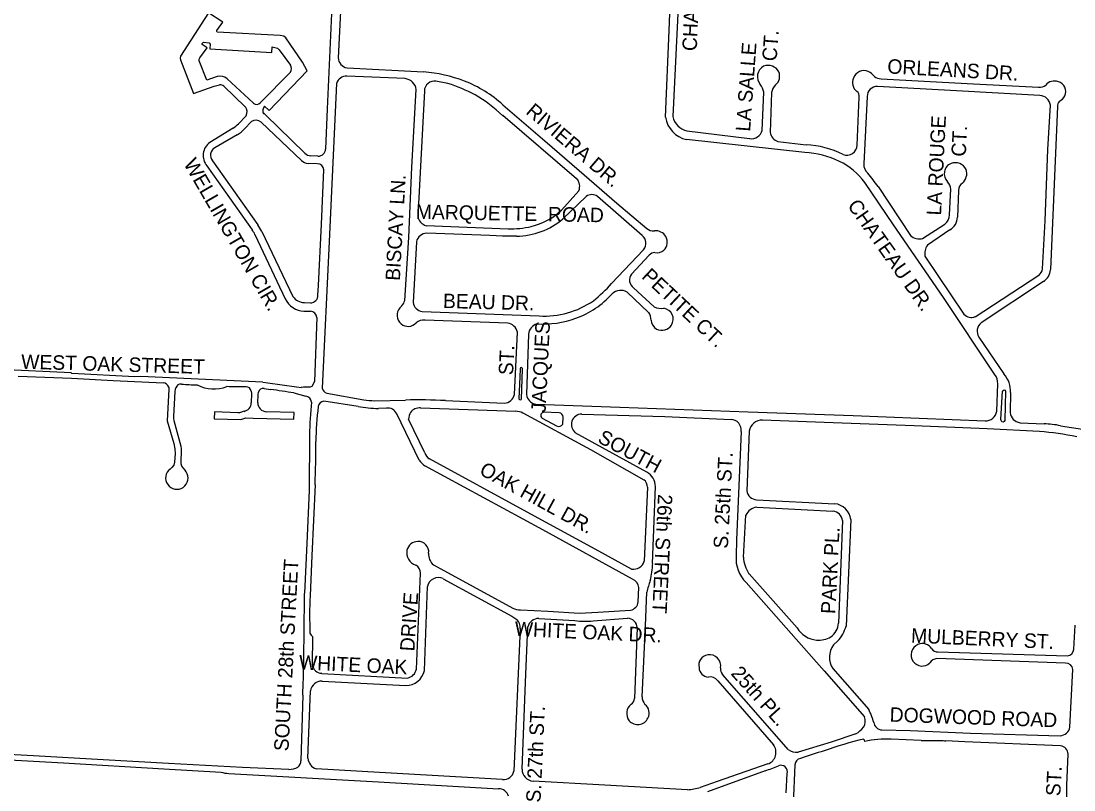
# Model space of a CAD drawing. Extents: x 0 to 712119, y 0 to 761125.
# Drawn here: x 674515 to 678156, y 731363 to 734022 of the extents above; entities that cross this region are included whole.
import ezdxf

# ---------------------------------------------------------------- set-up
doc = ezdxf.new("R2010")
doc.units = 0
doc.layers.add('PAVED ROADS', color=7, linetype='Continuous')
doc.layers.add('street names', color=7, linetype='Continuous')

msp = doc.modelspace()

# ---------------------------------------------------------------- linework, layer by layer
at = {"layer": 'PAVED ROADS'}
for points in [[(675652.2, 735319), (675637.3, 735042.7), (675627.5, 734773.9), (675618.5, 734577.2), (675593, 734058.8), (675589.4, 734048.4), (675573.9, 733717.9), (675568.3, 733578.6)], [(676743.3, 733689), (676756.4, 733989.1), (676770.1, 734344.8), (676784.9, 734648.6)], [(676811.5, 734637.9), (676790.9, 734143.3), (676768.9, 733691.7)], [(675643.4, 734593), (675628.8, 734239.8), (675611.9, 733895)], [(675357.3, 733727.5), (675373.1, 733713), (675505.1, 733849.5), (675488.9, 733879.7), (675430.4, 733963.3), (675424.3, 733970.1), (675411.8, 733971.3), (675194, 733983.8), (675192.2, 733985.5), (675192.9, 733988.9), (675213.1, 734018.2), (675163.7, 734050.5), (675066.3, 733900.6), (675065.2, 733893.5), (675066.8, 733887.7), (675111.2, 733770.7), (675183.5, 733797), (675202.1, 733801.4)], [(675194, 733829.7), (675157.6, 733817.3), (675131.6, 733884.1), (675131.1, 733890.5), (675133.3, 733894.8), (675158.7, 733929.1), (675141.5, 733941.2), (675141.9, 733944.6), (675145.8, 733948.4), (675166, 733946.4), (675169.7, 733941.6), (675168.2, 733925.4), (675382.5, 733913.5), (675384, 733932.7), (675393.4, 733930.9), (675401.8, 733928.1), (675408.4, 733922.7), (675446.8, 733869.8)], [(675446.7, 733845.2), (675343.8, 733739.9)], [(675642.9, 733860.2), (675907.1, 733846.1)], [(675317.5, 733738.7), (675228.3, 733822.5)], [(675606.7, 733806.3), (675581.1, 733258.9), (675557, 732752.4)], [(675843.6, 733822.7), (675642, 733831.2)], [(675991.3, 733806), (675949.9, 733814.1)], [(677489.1, 733822.2), (677787.1, 733806.1), (678033.7, 733793.3)], [(675216.8, 733797.1), (675290.9, 733725.1)], [(675841.9, 733055.6), (675855.9, 733272.9), (675866.6, 733516.4), (675881.6, 733784.8)], [(675909.9, 733780.6), (675887.1, 733346)], [(677077.7, 733643.8), (677083.6, 733775.9)], [(677110.8, 733774.5), (677105.6, 733636.7)], [(678038, 733763.9), (677749.6, 733780.1), (677477.2, 733795.3)], [(676181.6, 733732), (676326.5, 733607.9), (676444.7, 733505.1), (676575.8, 733391.9), (676679, 733304.6)], [(677406.7, 733592.9), (677413.5, 733758.6)], [(677441, 733761.2), (677429.4, 733527.6)], [(678047.8, 733164.4), (678056.2, 733331.1), (678066.1, 733577.2), (678074.5, 733730.9)], [(675293.3, 733693.7), (675266.9, 733666.8)], [(675496.9, 733564.5), (675360.2, 733697.6), (675355.9, 733702.5), (675353.5, 733700.9)], [(676436.4, 733476.5), (676181.2, 733694.6)], [(678099.1, 733726.2), (678075.1, 733162)], [(675312.6, 733674.1), (675287.6, 733649.3)], [(675484.7, 733540.1), (675345.3, 733672.2)], [(675248.3, 733651.6), (675168.6, 733602.2)], [(675262.9, 733627.8), (675185.8, 733583.4)], [(676817.9, 733641.9), (677034.7, 733615.4)], [(677225.1, 733567.1), (676816.7, 733612)], [(677132.4, 733605.3), (677229.9, 733594.2)], [(675542.1, 733554.8), (675516.4, 733556.1)], [(675158.1, 733521.3), (675314.5, 733300.1)], [(675177.9, 733538.7), (675333.8, 733317.3), (675333.8, 733317.3)], [(675539.7, 733528.5), (675508.1, 733529.3)], [(675542, 733074.2), (675543.4, 733107.6), (675554.3, 733319), (675562.5, 733506.7)], [(677881.8, 732800.1), (677704.8, 733065.3), (677531.6, 733316.8), (677432.8, 733463.1)], [(677478.7, 733449.7), (677591.4, 733280.3)], [(677725.6, 733351.4), (677730.3, 733440.2)], [(676383.9, 733368.2), (676443.9, 733435)], [(676469.2, 733415.3), (676389.2, 733337.7)], [(676663.4, 733280.4), (676509, 733415.1)], [(677757.2, 733436.1), (677753.1, 733343.8)], [(675347.8, 733294.2), (675455.6, 733068.9)], [(675915.7, 733314.2), (676199.5, 733303.3)], [(677632.9, 733270.3), (677710.1, 733319)], [(677726.8, 733300.1), (677649.4, 733246.7)], [(675324.2, 733283.5), (675429.2, 733061.1)], [(675882.5, 733258.8), (675870.9, 733047.9)], [(676228.4, 733277.3), (676180.3, 733277.9), (676136.7, 733280.1), (675918.4, 733288.2)], [(676557.4, 733114.6), (676667.9, 733231)], [(676687.8, 733211.7), (676626.4, 733146.2)], [(677640.9, 733208.6), (677775.7, 733007.9)], [(677814.7, 732999.4), (678035, 733142.4), (678035, 733142.4)], [(678050.5, 733121.2), (677835.1, 732978.1)], [(676685.5, 733013.9), (676611, 733084.6)], [(676633.3, 733099.6), (676704.7, 733033.3)], [(675494.9, 733048.1), (675515.9, 733046.8)], [(676494.4, 733054.7), (676494.4, 733054.7)], [(676494.4, 733054.7), (676494.4, 733054.7)], [(675493.5, 733018.2), (675516.2, 733018.6)], [(675824.8, 733029.8), (675832.5, 733036.9)], [(675901.9, 733017), (676306.8, 733001.8)], [(675538.2, 732996.2), (675529.5, 732774.7), (675521.1, 732758.4), (675514.8, 732755.2)], [(676198, 732977.4), (675912.1, 732987), (675912.1, 732987)], [(676221.4, 732730.3), (676231.5, 732945.9)], [(676269.7, 732938.7), (676263.1, 732729.8)], [(677827.4, 732929), (677913.9, 732801.4)], [(675351.8, 732772.4), (674929.5, 732793), (674908.9, 732791.2), (674690.8, 732802.7), (674688.2, 732805.3), (674442.7, 732816.9)], [(674505.8, 732794.2), (674689.4, 732786.7), (674833.5, 732778.8), (675006.8, 732771)], [(676241.1, 732818.3), (676236.9, 732714.8)], [(676246.2, 732714.8), (676249.1, 732818.3)], [(675026.1, 732755.9), (675026.5, 732748.2), (675021, 732638.7), (675043.8, 732561.2), (675047.7, 732542), (675048, 732526.6), (675046.5, 732496.8), (675043.1, 732485.8), (675036.5, 732477.3), (675030.7, 732472.4)], [(675086.5, 732462.6), (675082.9, 732468.6), (675076.7, 732475.3), (675071.8, 732482.3), (675069.4, 732490.6), (675068.9, 732496.2), (675070.5, 732536.6), (675070.1, 732543.3), (675068.8, 732550.8), (675045.4, 732638.9), (675043.8, 732648), (675043.9, 732653.8), (675048.8, 732741.1), (675049.2, 732747.1), (675050.8, 732753.4)], [(675355.6, 732751.4), (675378.1, 732748.1)], [(675484.5, 732754.8), (675484.5, 732754.8)], [(677889.2, 732672.9), (677892.3, 732767.1)], [(675311.1, 732741.9), (675312.5, 732733.5), (675311.1, 732701.2)], [(675334, 732702), (675334.9, 732729.4), (675336.2, 732738.7)], [(675458.7, 732735.6), (675500.1, 732724.8)], [(675572.9, 732735), (675700.2, 732711.4)], [(675737.5, 732708.7), (675844.5, 732711.1)], [(677936.9, 732736.6), (677935.8, 732668.5)], [(675680.7, 732688.6), (675562.7, 732707.3)], [(675778.8, 732682.8), (675751.3, 732682.3)], [(675896.8, 732683.7), (676226.1, 732672.5)], [(675983, 732709.1), (676186.2, 732700.2)], [(676295.7, 732697.2), (676586.2, 732686.7), (677029.4, 732670.7), (677392.8, 732657.2), (677848.5, 732639)], [(675286.7, 732672.1), (675270.8, 732667.4), (675265.2, 732667.3), (675184.6, 732669.8), (675182.9, 732646.1), (675275, 732643.9), (675292.6, 732649.5), (675317.8, 732648.9), (675458.8, 732645.2), (675459.5, 732668.4), (675364.1, 732670.7)], [(675891.9, 732502.9), (675814.2, 732663.6)], [(675911.2, 732528.3), (675855.5, 732644.7)], [(676250.6, 732666.3), (676484.5, 732539.7), (676669.1, 732435.2)], [(676317.2, 732648.9), (676367, 732621.6)], [(676375.9, 732666.9), (676322.1, 732668.6)], [(676375.9, 732666.9), (676375.9, 732666.9)], [(676388.6, 732627.8), (676390.2, 732652.2)], [(676454.1, 732662.7), (676741.3, 732653.6), (676970.3, 732644.3)], [(678036.5, 732602.1), (677855.7, 732611.5), (677603.7, 732621.8), (677292.4, 732632.9), (677079, 732641.3)], [(677005.4, 732602.4), (676988.8, 732227.6), (676987.8, 732172.6)], [(677033.3, 732603.6), (677024.8, 732397)], [(677969.9, 732632.8), (678053, 732628.9)], [(678109.2, 732622.2), (678185.1, 732610.3)], [(675513, 732590), (675512, 732399), (675503.2, 732214.7), (675495.5, 732042.6)], [(676679.7, 732461.1), (676431.9, 732598.1)], [(676626.6, 732126.5), (676512.9, 732188.3), (676265.3, 732323.6), (675927.2, 732507.3)], [(676629.8, 732091.5), (676319.1, 732261.9), (675911.5, 732483.8)], [(675531.9, 732418.3), (675520.6, 732173.4), (675514.7, 732034.4)], [(676681, 732409.4), (676670.2, 732154)], [(676699.3, 732145.8), (676709.1, 732412)], [(677058.4, 732365.8), (677328.9, 732352.6)], [(677013, 732167.9), (677021.3, 732313.4)], [(677059, 732340.6), (677322.9, 732327.3)], [(677356, 732294), (677342, 731939.2)], [(677384.6, 732297.5), (677367.9, 731929.3)], [(675941.5, 732141), (676078.9, 732066.5), (676215.4, 731991.5)], [(675882.2, 731780.7), (675896.1, 732112.3)], [(675974.7, 732093.3), (676212.1, 731963.5), (676230, 731952.6)], [(675974.7, 732093.3), (675974.7, 732093.3)], [(677198.9, 731922.9), (677032.5, 732109.9), (677032.5, 732109.9)], [(675910.2, 731775.8), (675921.2, 732066)], [(676649.4, 732012.9), (676651.5, 732063)], [(677022.3, 732080.3), (677178.7, 731903.9), (677292.4, 731774.3), (677431.3, 731615)], [(676662.7, 731684.8), (676674.4, 731930.4), (676679, 732046.6)], [(676242.1, 731985.8), (676336.4, 731980.9), (676446.2, 731974.2), (676510, 731977.5), (676622.9, 731984.5)], [(676305.2, 731955.7), (676430.2, 731948.1)], [(676493.7, 731947.3), (676612.5, 731956.4)], [(676240.9, 731920.6), (676219.8, 731427.3)], [(676247.8, 731434.1), (676259.8, 731735.8), (676267.3, 731927)], [(676646.1, 731923.9), (676636, 731679)], [(678156, 731849.9), (678160.6, 731932.7)], [(675523.7, 731893.6), (675522.3, 731795.3)], [(677338.8, 731877.7), (677324.8, 731864.1)], [(677685.6, 731840.3), (678132.4, 731826.1), (678132.4, 731826.1)], [(678126.5, 731801.6), (677681.6, 731817.2)], [(675555.1, 731765.9), (675851.1, 731749.7)], [(677322.1, 731782.7), (677446.4, 731640.3)], [(678142.2, 731580), (678152.1, 731779.2)], [(675556.2, 731738.9), (675845.7, 731723.5)], [(676924.2, 731739.8), (677117, 731519.1)], [(677168, 731503), (677088.6, 731593.4), (676941.1, 731762.4)], [(675489.7, 731690.5), (675483.2, 731463.2)], [(675507.5, 731472.3), (675516.1, 731705.8)], [(677402.3, 731556.4), (677316, 731528), (677202, 731493.5)], [(677491.9, 731570.1), (677590, 731567.7), (677798.6, 731558.9), (678108.4, 731549.8)], [(677627.5, 731534), (677524.4, 731538)], [(678109.5, 731515), (677778.5, 731529.5), (677713.4, 731533)], [(674172.6, 731477.8), (674349.6, 731473.2), (674661.6, 731456.3), (675009, 731435.2), (675207, 731424.2)], [(675441.3, 731433.7), (675281.2, 731440.6), (675024.7, 731454), (674799.1, 731466.4), (674558.3, 731481.1), (674280, 731495.2)], [(678130, 731190.5), (678131.5, 731379), (678136, 731486.5)], [(676180.5, 731398.5), (675754.5, 731423.5), (675535.5, 731435.5)], [(677098, 731452.5), (676922, 731392), (676864, 731371.5)], [(677190.5, 731450), (677185, 731313)], [(675233.5, 731419.7), (675751.7, 731390.3), (676166.8, 731366.9)], [(677088.5, 731428.4), (676888.6, 731356)], [(677161.5, 731352.5), (677164.5, 731419)], [(676820, 731363.5), (676534, 731379.5), (676286.5, 731393)]]:
    msp.add_lwpolyline(points, dxfattribs=at)
msp.add_lwpolyline([(677915, 732746), (677918.7, 732744.8), (677919.9, 732742), (677916.9, 732640.4), (677914.3, 732636.5), (677910.8, 732634.8), (677907.1, 732636.2), (677904.3, 732640.2), (677903.8, 732644.1), (677909.2, 732741.8), (677911.3, 732744.6)], close=True, dxfattribs=at)
for centre, radius, start, end in [((675647.6, 733895.7), 35.8, 181.1063, 262.3574), ((675427.6, 733857.6), 22.7, 326.7538, 32.4129), ((675863.5, 733319.3), 528.6, 69.4388, 85.2607), ((677102.1, 733829.5), 40.7, 117.8036, 221.238), ((677099, 733827.9), 40.7, 26.4491, 112.8896), ((677100.2, 733830.7), 38.4, 309.0638, 23.5384), ((677430.2, 733811.2), 39.1, 67.8293, 159.5623), ((677415.2, 733789.8), 64.9, 38.282, 62.7128), ((675204, 733792), 39, 51.5443, 104.8205), ((675640.1, 733796.3), 34.9, 86.9787, 163.3541), ((675839.7, 733780.8), 42.1, 5.376, 84.6785), ((675945.4, 733778.8), 35.6, 82.7111, 177.0378), ((675791.7, 733193.7), 644, 62.8509, 71.944), ((675892.4, 733414.2), 429.6, 47.702, 68.6129), ((677014.7, 733760.8), 70.5, 12.3455, 36.3415), ((677431.2, 733809.4), 40.7, 157.6485, 230.1123), ((677493.8, 733874), 52, 237.9363, 264.8852), ((678088.1, 733775.8), 38.5, 68.4961, 140.7166), ((678093, 733778), 34.9, 334.9812, 74.6891), ((675203.4, 733778.8), 22.7, 53.8442, 93.2968), ((675782.9, 733266.6), 584.6, 47.06, 58.8231), ((677156, 733767.8), 45.8, 133.699, 171.5813), ((677394.8, 733762.2), 19.1, 349.2433, 57.057), ((677475.3, 733761), 34.3, 86.9844, 179.682), ((678037.6, 733827), 33.9, 263.499, 307.8141), ((675319.5, 733739.4), 2.14, 199.8502, 231.3778), ((675329.9, 733752.3), 18.7, 231.3778, 318.1777), ((678037.9, 733727.1), 36.8, 5.8627, 89.8687), ((678128.5, 733726.2), 29.4, 142.4675, 179.9221), ((678086.8, 733782.2), 42.3, 295.7747, 333.4424), ((675268.8, 733707.6), 28.2, 330.3899, 38.3732), ((675374.2, 733711.5), 23.2, 136.6053, 207.2551), ((675186.7, 733746), 112.7, 303.119, 315.3728), ((675327.6, 733650.7), 27.9, 50.5728, 122.5743), ((676837.6, 733705.4), 95.7, 189.8361, 257.4042), ((676833.2, 733705.9), 65.9, 192.4425, 256.537), ((675194.4, 733731.2), 124, 303.5207, 318.6947), ((677040.8, 733653), 38, 260.8956, 346.0059), ((677144, 733642.3), 38.8, 188.3597, 252.5533), ((675199.8, 733557), 54.9, 124.637, 220.5561), ((675198.4, 733558.1), 28.3, 116.6622, 223.4804), ((677211.8, 733266.9), 327.8, 63.5385, 86.8327), ((677371.2, 733593.2), 35.5, 247.8932, 359.4094), ((675517.9, 733586), 30, 225.77, 267.27), ((675543.3, 733579.8), 25, 267.27, 357.27), ((677211.4, 733263.1), 304.3, 63.9305, 87.4151), ((675512.3, 733568.9), 39.9, 226.2483, 263.909), ((675539.5, 733505.5), 23, 3.0595, 89.4272), ((677251.5, 733335.3), 221.8, 35.1621, 65.047), ((677469.4, 733525.7), 40, 177.2223, 229.6471), ((677745.8, 733493.9), 38.5, 112.3661, 226.5194), ((677745.2, 733489.9), 42.1, 26.114, 109.5804), ((676409.3, 733450.2), 37.8, 336.4498, 44.1708), ((676316.8, 732587.1), 1447.1, 36.5897, 38.8661), ((677742.9, 733494.2), 42.5, 309.9211, 19.56), ((677687.2, 733437), 43.2, 4.2668, 42.128), ((677790, 733435.4), 32.8, 126.9928, 178.8692), ((676489, 733388.1), 33.6, 53.3559, 126.133), ((676230, 733527), 221.2, 282.9575, 314.0964), ((675927.1, 733353.2), 40.7, 190.2197, 253.6345), ((676223.5, 733534.7), 257.4, 271.083, 310.0681), ((677675.8, 733355.3), 50, 313.4119, 355.4929), ((677703.3, 733344), 49.8, 298.1983, 359.7485), ((675224.7, 733236.6), 110, 25.27, 35.27), ((675198.6, 733219.8), 166.7, 26.5049, 35.7949), ((676208.7, 733611.7), 308.5, 268.3018, 283.2796), ((676700.8, 733329), 32.8, 228.1546, 277.6857), ((676708.8, 733253.8), 42.9, 32.3425, 94.73), ((675919.8, 733249.8), 38.4, 92.0928, 166.5044), ((676639.9, 733253.4), 35.8, 321.3942, 49.0431), ((676709.6, 733257.8), 40.2, 315.1427, 28.1229), ((677620.7, 733310.9), 42.4, 226.2029, 286.739), ((676705.1, 733200.1), 20.8, 85.1682, 146.2518), ((676714.1, 733255.8), 35.7, 258.3652, 312.2399), ((677688.7, 733218), 48.7, 143.8222, 191.1188), ((678004.7, 733174.7), 44.3, 313.0845, 346.6018), ((678021.7, 733166.3), 53.5, 302.4864, 355.3571), ((676244.3, 733380.7), 410.9, 307.5021, 319.6362), ((676650.9, 733126), 31.7, 140.4101, 236.337), ((675514.5, 733074.3), 27.5, 272.9977, 359.7926), ((676325.1, 733290.3), 315.8, 290.1347, 317.8659), ((676589.4, 733046.9), 43.5, 60.2005, 133.6146), ((675497, 733093.1), 75, 205.27, 267.27), ((675494.8, 733095.4), 47.2, 214.0471, 270.149), ((675805.6, 733062.2), 36.9, 316.8125, 349.735), ((675907.5, 733053.7), 37.1, 188.8657, 261.221), ((676323.9, 733300.3), 299, 266.7254, 304.7771), ((675515.1, 732995.4), 23.1, 1.9088, 87.3388), ((675855.1, 733004.5), 39.5, 140.1132, 229.0189), ((676649.4, 732988), 44.5, 358.9922, 35.694), ((676730.2, 733090.5), 62.7, 245.9104, 277.2193), ((676732.3, 732990.8), 38, 327.8349, 81.205), ((677801.5, 733032.5), 35.6, 223.7731, 291.8248), ((675853.7, 733004.2), 38.3, 230.3108, 317.3506), ((675905.2, 732954.5), 33.2, 77.9027, 134.6007), ((676192.5, 732938), 39.8, 11.5163, 82.049), ((676311.7, 732934.4), 42.2, 106.9099, 174.1988), ((676322, 733301.3), 327.3, 266.0564, 289.9889), ((676732.5, 732990.1), 38.7, 184.2934, 239.9138), ((676731, 732992.1), 39.8, 243.2654, 327.231), ((677858.6, 732949.2), 37.2, 129.1035, 212.9711), ((676245.1, 732819.1), 4.07, 348.5463, 192.0652), ((677847.5, 732771), 45, 355.004, 40.2416), ((677847, 732741.2), 90, 357.09, 42.0009), ((675005.1, 732748.9), 22.2, 18.3413, 85.5429), ((675068.4, 732747.8), 18.6, 85.581, 162.1926), ((675139.4, 733547.5), 784.3, 264.9165, 268.9035), ((675182.4, 732875.7), 126.5, 242.6871, 290.7161), ((675206.8, 728398.5), 4358.9, 88.8635, 89.7321), ((675294.6, 732740), 16.6, 6.5677, 94.6132), ((675352.3, 732735.3), 16.4, 78.2767, 168.0579), ((679549.8, 763896.8), 31406.2, 262.31841, 262.5627), ((674363.5, 725937.6), 6885.6, 80.84787, 81.52596), ((675501.1, 732649.1), 107, 82.6675, 98.9424), ((675578.3, 732755.7), 21.5, 188.873, 255.4961), ((675496.4, 732701.9), 23.3, 5.9048, 80.7137), ((675741.9, 733026.5), 317.8, 262.4569, 269.2161), ((675889.8, 731072.6), 1639.1, 86.7392, 91.5842), ((676184.2, 732738.1), 38, 272.9263, 348.1652), ((676241.6, 732716.9), 5.1, 203.3617, 336.2201), ((676299.8, 732734), 37, 186.4758, 263.5534), ((675281.9, 732700.8), 29.2, 279.5364, 0.7653), ((675365, 732701.7), 31.1, 179.4419, 268.3504), ((676879.3, 732568.6), 1366.5, 174.3033, 179.104), ((676580.2, 732554.8), 1045.8, 172.6506, 179.31), ((675566.8, 732683.3), 24.4, 99.7837, 167.3358), ((675751.4, 733078.2), 395.9, 259.7237, 269.9979), ((675784.7, 732651.4), 31.9, 22.4585, 100.5998), ((675892.7, 732646.3), 37.6, 83.7236, 143.8939), ((675896.7, 732645.6), 41.3, 146.4839, 181.3167), ((676224.2, 732613.5), 59, 63.3714, 88.1307), ((676323, 732657.9), 10.7, 94.3193, 237.4598), ((676373.5, 732650.3), 16.9, 6.5014, 81.6123), ((676454.8, 732626.4), 36.4, 91.1249, 230.93), ((676968.5, 732607.2), 37.2, 352.5695, 87.3339), ((677076.3, 732598.1), 43.4, 86.5043, 172.7132), ((677849.4, 732679.3), 40.3, 268.7154, 350.9241), ((677973.1, 732670), 37.3, 182.3202, 265.1013), ((676374.6, 732636), 16.3, 242.2286, 329.5719), ((677947.4, 731478.9), 1126.8, 78.8034, 85.4651), ((678043, 732309.1), 320, 78.0495, 88.2127), ((672688.1, 732541.7), 2846.5, 357.5141, 0.5169), ((675530.7, 732567.5), 3.74, 358.7249, 358.8022), ((675958.6, 732547.9), 51.3, 202.4264, 232.2873), ((675951.5, 732544.5), 72.7, 214.9326, 236.6011), ((675054, 732441.3), 38.9, 126.7873, 33.1534), ((676649.4, 732409.6), 59.8, 2.3208, 59.5228), ((676653.2, 732412.2), 27.9, 354.2968, 55.3129), ((677061.9, 732403.3), 37.7, 189.7135, 264.6662), ((677322.6, 732290.6), 62.3, 6.3952, 84.2465), ((677066, 732291.3), 49.8, 98.0569, 153.626), ((677317.1, 732288.4), 39.3, 8.1404, 81.4161), ((675887.7, 732182.8), 39.1, 91.1765, 166.5834), ((675889.1, 732185.9), 36, 352.7831, 93.4229), ((675894.4, 732183.7), 45.5, 169.6736, 251.9465), ((675972.4, 732177.4), 47.8, 175.2087, 229.6467), ((677103.7, 732163.2), 116.2, 175.4007, 225.5429), ((677130, 732175), 117.3, 183.4477, 213.7144), ((675862.5, 732112), 33.6, 0.4792, 57.9057), ((676632.8, 732165.2), 39.1, 260.9486, 343.3139), ((676366.3, 732162), 333.5, 346.9678, 357.2151), ((675958, 732059.9), 37.4, 63.4665, 170.4664), ((676612.9, 732056.1), 39.2, 10.1856, 64.5862), ((677023.4, 731964.1), 354.2, 159.7404, 166.5411), ((661781.6, 732158.8), 13714.5, 358.98699, 359.51423), ((676906.1, 731965.8), 1393, 177.1756, 182.5188), ((676242.2, 732051.3), 65.6, 245.8982, 269.9215), ((676617.2, 732016.4), 32.4, 280.1318, 353.7859), ((676197.7, 731923.7), 43.4, 355.9121, 41.845), ((676306.1, 731915), 40.7, 91.219, 162.806), ((676465.6, 732220.4), 274.6, 262.595, 275.8748), ((676612.2, 731922.5), 33.9, 2.3146, 89.3673), ((669599.7, 731911.9), 5894.2, 357.84711, 0.04354), ((677273.1, 731967.4), 86.5, 210.9666, 265.2972), ((677279.7, 731943.3), 62.4, 304.9476, 356.2283), ((677257.9, 731957.3), 113.5, 315.4566, 345.7144), ((675533, 731911), 19.7, 198.9591, 241.7544), ((677273.5, 731964.1), 83.3, 264.8583, 300.2718), ((677382.2, 731821.4), 71.5, 143.4013, 212.7852), ((677632.2, 731829.6), 39.3, 113.4299, 215.3458), ((677632.1, 731831.4), 37.6, 31.1778, 114.4056), ((677684.1, 731864.2), 23.9, 213.857, 273.603), ((678130.8, 731851.3), 25.3, 273.6067, 356.7659), ((676895, 731793.8), 36.4, 98.1561, 193.6888), ((676896.2, 731791.8), 38.6, 349.1571, 99.4269), ((677631.1, 731829), 38, 215.5835, 314.3788), ((677686.5, 731783.5), 34.1, 98.3095, 147.4287), ((678127, 731776.3), 25.3, 6.551, 91.0443), ((675556.6, 731800.7), 34.8, 188.9236, 267.4174), ((675845.1, 731790.1), 66.7, 270.5836, 347.6259), ((675845.4, 731786.6), 37.3, 278.8093, 351.0458), ((676893.7, 731787.2), 34.1, 183.4639, 266.9647), ((676962.5, 731781.4), 28.6, 173.6348, 221.4946), ((675555.3, 731699.2), 39.8, 88.7488, 170.4117), ((676897.3, 731720.4), 33.1, 35.8096, 99.3713), ((676650.2, 731627), 40.8, 127.2483, 217.7801), ((676614.2, 731678.1), 21.9, 301.1627, 2.1877), ((676708.7, 731687.3), 46.1, 183.1936, 218.5396), ((676649, 731628.5), 38.2, 332.9296, 51.7688), ((677302.3, 731558.8), 165.6, 13.1055, 29.4805), ((676647.5, 731627.8), 39.2, 221.0256, 334.9307), ((677393.4, 731599.7), 40.8, 329.8926, 21.8896), ((677494.1, 731601), 30.9, 188.548, 265.9049), ((677319.8, 731679), 147.7, 303.9488, 317.5403), ((678104.9, 731587.8), 38.1, 275.2423, 348.208), ((677082.6, 731492.9), 43.2, 290.8692, 37.235), ((677694.5, 730404.2), 1165, 103.1715, 110.1973), ((677472.6, 731552.8), 45.9, 198.1654, 209.0934), ((677504.6, 731213.4), 325.2, 86.5087, 102.8058), ((677687.8, 735137.4), 3603.9, 269.0413, 270.0906), ((677709.3, 731755.8), 222.8, 265.9445, 271.0603), ((678105.4, 731484.6), 30.6, 3.5014, 82.3335), ((675549, 731474.8), 41.6, 183.412, 251.1103), ((677194.9, 731533.7), 40.8, 228.7433, 280.0347), ((677590.8, 730410.4), 1127.4, 105.3582, 109.7434), ((675439.9, 731506.9), 73.2, 271.0712, 296.806), ((675454.5, 731463.5), 28.7, 310.0897, 359.4035), ((676293.8, 733488.1), 2207.7, 291.0968, 292.3685), ((677142.2, 731424.9), 23.1, 345.2377, 110.6842), ((677216.1, 731446.4), 25.8, 103.5698, 172.0156), ((675240.1, 731536.9), 117.5, 253.6645, 266.7928), ((676182.1, 731437.5), 39.1, 267.5915, 344.891), ((676289, 731433.6), 41.2, 179.3926, 221.1835), ((676290.5, 731438.3), 45.4, 224.3462, 264.9614), ((676166.5, 731331.2), 35.7, 16.6024, 89.4348), ((676810.2, 731542.2), 179, 273.1269, 287.4827)]:
    msp.add_arc(centre, radius, start, end, dxfattribs=at)

# ---------------------------------------------------------------- texts
at = {"layer": 'street names'}
for s, rotation, p in [('CHATEAU DR.', 87.4556, (676851.5, 733917.2)), ('CT.', 85.8342, (677127.6, 733881.7)), ('LA SALLE', 85.8342, (677036.2, 733638.4)), ('ORLEANS DR.', 356.7845, (677509.7, 733840.9)), ('RIVIERA DR.', 319.5772, (676257.5, 733703.6)), ('LA ROUGE', 87.1362, (677696.4, 733348.6)), ('CT.', 87.1362, (677781.8, 733551.9)), ('WELLINGTON CIR.', 299.9953, (675075.9, 733528.7)), ('BISCAY LN.', 86.7943, (675825.2, 733122.5)), ('CHATEAU DR.', 305.2391, (677370.8, 733383.4)), ('MARQUETTE  ROAD', 358.9504, (675880.1, 733337.6)), ('PETITE CT.', 316.9191, (676658.6, 733135.3)), ('BEAU DR.', 358.4739, (675973.8, 733029.5)), ('JACQUES', 87.2247, (676329.2, 732666.8)), ('ST.', 87.2247, (676216.4, 732796.3)), ('WEST OAK STREET', 358.3605, (674515.1, 732819.5)), ('SOUTH', 331.9088, (676505.8, 732567)), ('OAK HILL DR.', 331.1596, (676096.5, 732456.2)), ('S. 25th ST.', 87.0419, (676959.3, 732196.3)), ('26th STREET', 267.193, (676718, 732386.2)), ('PARK PL.', 87.1461, (677331, 731970.3)), ('SOUTH 28th STREET', 87.0061, (675439.9, 731495.5)), ('DRIVE', 86.1938, (675875.3, 731840.9)), ('WHITE OAK DR.', 357.4096, (676221.6, 731895.4)), ('MULBERRY ST.', 357.4331, (677592, 731872.3)), ('WHITE OAK', 357.4096, (675475.4, 731779.3)), ('25th PL.', 311.8933, (676967.3, 731763.8)), ('S. 27th ST.', 87.3249, (676311.5, 731318.4)), ('DOGWOOD ROAD', 358.0379, (677518.2, 731598.9)), ('24th ST.', 86.9312, (678100.7, 731191.8))]:
    msp.add_text(s, height=50, rotation=rotation, dxfattribs=at).set_placement(p)

doc.saveas('drawing.dxf')
